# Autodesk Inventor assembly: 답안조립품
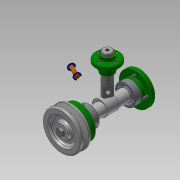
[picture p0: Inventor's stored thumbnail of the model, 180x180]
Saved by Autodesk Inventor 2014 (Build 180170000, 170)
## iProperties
Created: 2016-08
Part Number: 답안조립품
Document SubType Name: Assembly
Designer: user
Author: user
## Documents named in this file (17)
- C:\Users\user\Desktop\460820V1012\답안조립품.iam
- C:\Users\user\Desktop\460820V1012\본체.ipt
- C:\Users\user\Desktop\460820V1012\뒤커버.ipt
- C:\Users\user\Desktop\460820V1012\베어링 15 x 35 x 11.ipt
- C:\Users\user\Desktop\460820V1012\볼트 M4 x 10.ipt
- C:\Users\user\Desktop\460820V1012\앞커버.ipt
- C:\Users\user\Desktop\460820V1012\오일실 15 25 7.ipt
- C:\Users\user\Desktop\460820V1012\편심축.ipt
- C:\Users\user\Desktop\460820V1012\멈춤링 6 x 5.ipt
- C:\Users\user\Desktop\460820V1012\고정핀.ipt
- C:\Users\user\Desktop\460820V1012\멈춤링 15 x 1.ipt
- C:\Users\user\Desktop\460820V1012\키 5 x 5 x 14.ipt
- C:\Users\user\Desktop\460820V1012\볼트 M6 x 12.ipt
- C:\Users\user\Desktop\460820V1012\V-벨트풀리.ipt
- C:\Users\user\Desktop\460820V1012\상부부시.ipt
- C:\Users\user\Desktop\460820V1012\볼트 M3 x 8.ipt
- C:\Users\user\Desktop\460820V1012\슬라이드바.ipt
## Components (15 placed, 5 different names)
1. 고정핀:1
2. ISO 4018 M6 x 12:1 — 강체:9
3. V-벨트풀리:1 — 각도:3
4. ISO 4762 M4 x 10:2 — 강체:6
5. ISO 4762 M4 x 10:3
6. ISO 4762 M4 x 10:4
7. ISO 4762 M4 x 10:5
8. ISO 4762 M4 x 10:1 — 강체:3
9. ISO 4762 M4 x 10:6
10. ISO 4762 M4 x 10:7
11. ISO 4762 M4 x 10:8
12. ISO 4762 M3 x 8:1 — 강체:11
13. ISO 4762 M3 x 8:2
14. ISO 4762 M3 x 8:3
15. ISO 4762 M3 x 8:4
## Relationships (5: WeldJoint 4, Angle 1)
- 강체:3 [WeldJoint]: ISO 4762 M4 x 10:1
- 강체:6 [WeldJoint]: ISO 4762 M4 x 10:2
- 강체:9 [WeldJoint]: ISO 4018 M6 x 12:1
- 각도:3 [Angle]: V-벨트풀리:1
- 강체:11 [WeldJoint]: ISO 4762 M3 x 8:1
